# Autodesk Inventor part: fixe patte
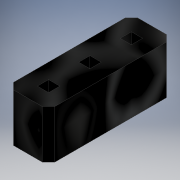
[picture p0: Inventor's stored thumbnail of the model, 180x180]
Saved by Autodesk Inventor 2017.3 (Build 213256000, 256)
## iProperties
Part Number: fixe patte
Material: Générique
Document SubType Name: Modeling
Designer: ficho
Density: 1 g/cm^3
Appearance: Noir
Author: ficho
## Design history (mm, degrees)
sketch "Esquisse1"
  geometry: L1 (1.245, -1.645)-(0.545, -1.645); L2 (1.245, -0.945)-(1.245, -1.645); L3 (0.545, -1.645)-(0.545, -0.945); L4 (0.545, -0.945)-(1.245, -0.945); L5 (2.19, -0.4)-(1.79, 0); L6 (0, 0)-(-0.4, -0.4); L7 (1.79, 0)-(0, 0); L8 (0.545, -3.525)-(1.245, -3.525); L9 (1.245, -3.525)-(1.245, -4.225); L10 (0.545, -4.225)-(0.545, -3.525); L11 (-0.4, -0.4)-(-0.4, -7.35); L12 (2.19, -7.35)-(2.19, -0.4); L13 (1.245, -4.225)-(0.545, -4.225); L14 (0.545, -6.105)-(1.245, -6.105); L15 (1.245, -6.105)-(1.245, -6.805); L16 (0.545, -6.805)-(0.545, -6.105); L17 (1.245, -6.805)-(0.545, -6.805); L18 (-0.4, -7.35)-(0, -7.75); L19 (0, -7.75)-(1.79, -7.75); L20 (1.79, -7.75)-(2.19, -7.35); 1 further point
  constraints: 40 end point
extrude "Extrusion1" new body sketch "Esquisse1" distance "d0" = 3; taper "d1" = 0 deg
node "Solide1"
